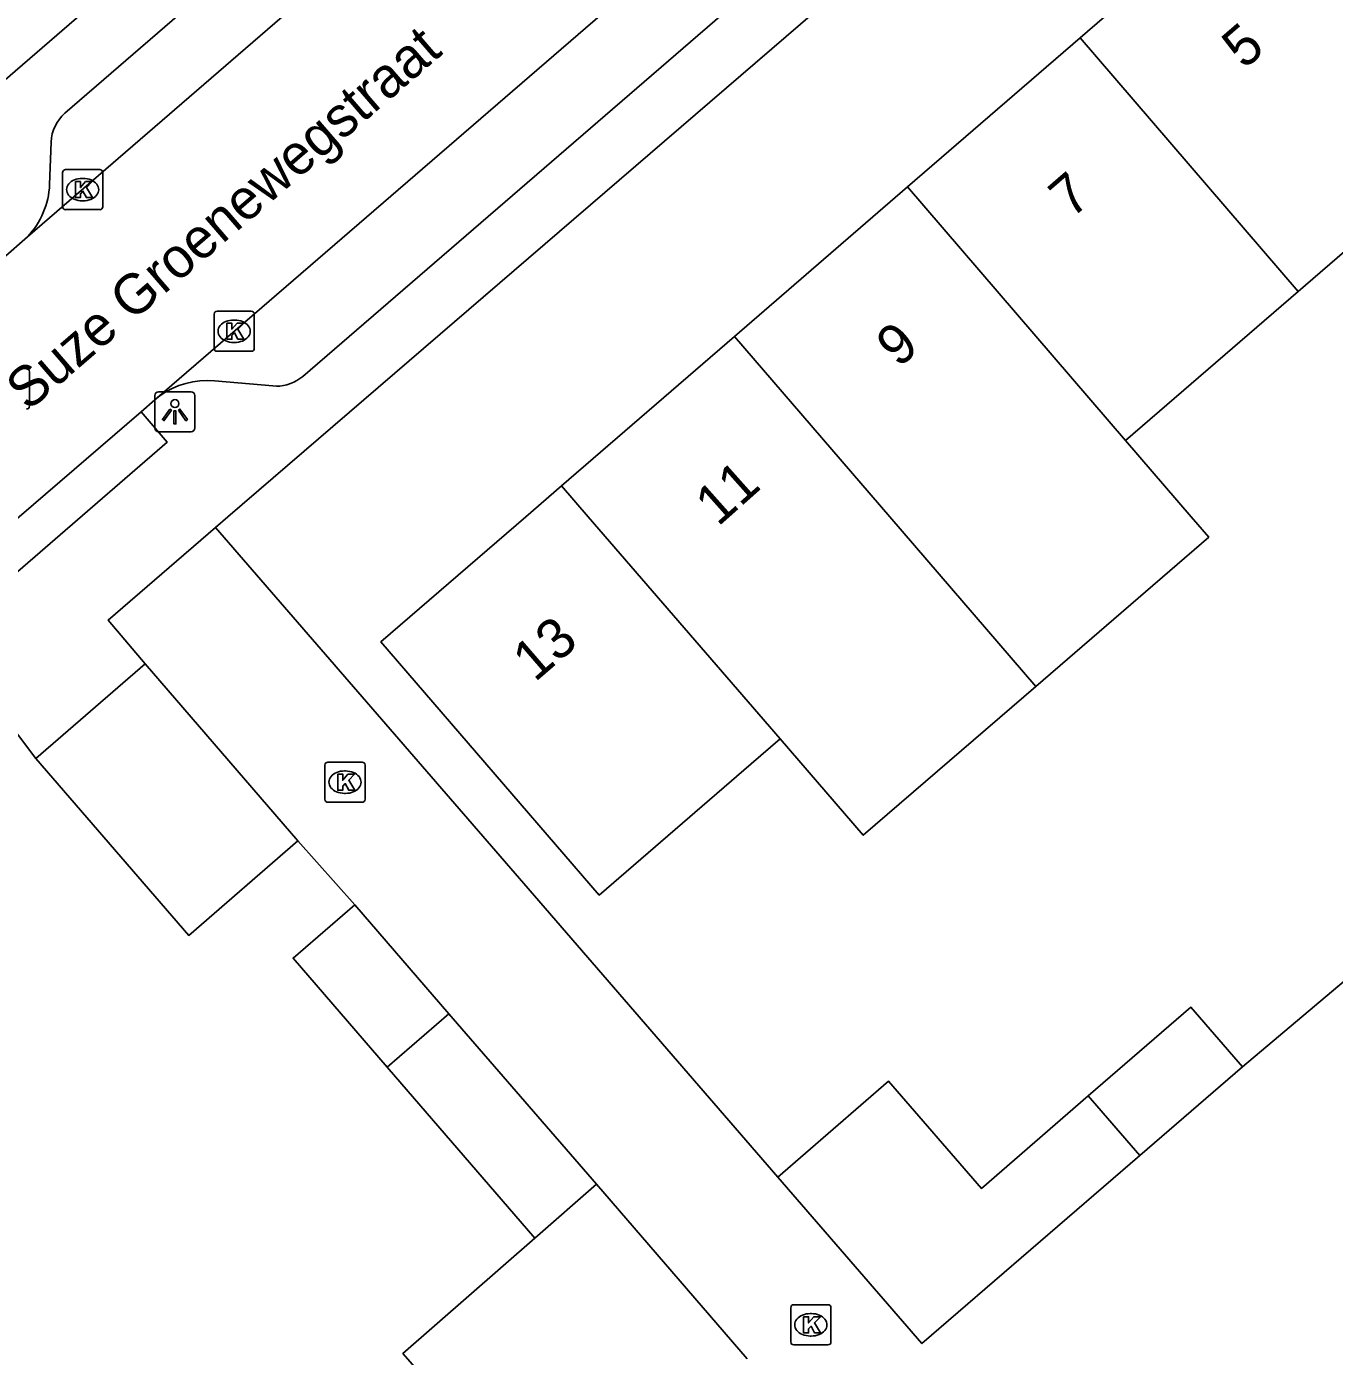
# Model space of a CAD drawing. Extents: x 160304 to 160954, y 383686 to 384161.
# Drawn here: x 160443.23 to 160475.81, y 383979.08 to 384012.21 of the extents above; entities that cross this region are included whole.
import ezdxf

# ---------------------------------------------------------------- set-up
doc = ezdxf.new("R2010")
doc.units = 0
for name, color, linetype in [('IMGEO_Kolk', 7, 'Continuous'), ('IMGEO_Lichtpunt', 7, 'Continuous'), ('IMGEO_Muur', 7, 'Continuous'), ('IMGEO_Openbare_ruimte_label', 7, 'Continuous'), ('IMGEO_Pand', 7, 'Continuous'), ('IMGEO_Pand_nummerreeks', 7, 'Continuous'), ('IMGEO_Rijbaan_lokaal_open', 7, 'Continuous'), ('IMGEO_Rioolput', 7, 'Continuous'), ('IMGEO_Voetpad_open', 7, 'Continuous')]:
    doc.layers.add(name, color=color, linetype=linetype)

msp = doc.modelspace()

# ---------------------------------------------------------------- linework, layer by layer
at = {"layer": 'IMGEO_Kolk'}
for p, q in [((160444.122, 384007.725), (160444.122, 384008.577)), ((160444.197, 384008.651), (160445.049, 384008.651)), ((160445.123, 384008.577), (160445.123, 384007.725)), ((160444.61, 384008.431), (160444.635, 384008.431)), ((160445.049, 384007.651), (160444.197, 384007.651)), ((160444.633, 384007.871), (160444.608, 384007.871)), ((160447.897, 384004.196), (160447.897, 384005.048)), ((160447.972, 384005.122), (160448.824, 384005.122)), ((160448.898, 384005.048), (160448.898, 384004.196)), ((160448.385, 384004.902), (160448.41, 384004.902)), ((160448.408, 384004.342), (160448.383, 384004.342)), ((160448.824, 384004.122), (160447.972, 384004.122)), ((160450.659, 383992.962), (160450.659, 383993.814)), ((160450.734, 383993.888), (160451.586, 383993.888)), ((160451.147, 383993.668), (160451.172, 383993.668)), ((160451.66, 383993.814), (160451.66, 383992.962)), ((160451.17, 383993.108), (160451.145, 383993.108)), ((160451.586, 383992.888), (160450.734, 383992.888)), ((160462.267, 383979.443), (160462.267, 383980.295)), ((160462.342, 383980.369), (160463.194, 383980.369)), ((160462.755, 383980.149), (160462.78, 383980.149)), ((160463.268, 383980.295), (160463.268, 383979.443)), ((160462.778, 383979.589), (160462.753, 383979.589)), ((160463.194, 383979.369), (160462.342, 383979.369))]:
    msp.add_line(p, q, dxfattribs=at)
for points in [[(160444.122, 384007.725), (160444.122, 384008.577)], [(160444.197, 384008.651), (160445.049, 384008.651)], [(160445.123, 384008.577), (160445.123, 384007.725)], [(160444.443, 384008.351), (160444.566, 384008.351), (160444.566, 384008.2), (160444.696, 384008.351), (160444.86, 384008.351), (160444.714, 384008.2), (160444.867, 384007.951), (160444.715, 384007.951), (160444.63, 384008.115), (160444.566, 384008.048), (160444.566, 384007.951), (160444.443, 384007.951), (160444.443, 384008.351)], [(160445.049, 384007.651), (160444.197, 384007.651)], [(160447.897, 384004.196), (160447.897, 384005.048)], [(160447.972, 384005.122), (160448.824, 384005.122)], [(160448.898, 384005.048), (160448.898, 384004.196)], [(160448.218, 384004.822), (160448.341, 384004.822), (160448.341, 384004.671), (160448.471, 384004.822), (160448.635, 384004.822), (160448.489, 384004.671), (160448.642, 384004.422), (160448.49, 384004.422), (160448.405, 384004.586), (160448.341, 384004.519), (160448.341, 384004.422), (160448.218, 384004.422), (160448.218, 384004.822)], [(160448.824, 384004.122), (160447.972, 384004.122)], [(160450.659, 383992.962), (160450.659, 383993.814)], [(160450.734, 383993.888), (160451.586, 383993.888)], [(160451.66, 383993.814), (160451.66, 383992.962)], [(160450.98, 383993.588), (160451.103, 383993.588), (160451.103, 383993.437), (160451.233, 383993.588), (160451.397, 383993.588), (160451.251, 383993.437), (160451.404, 383993.188), (160451.252, 383993.188), (160451.167, 383993.352), (160451.103, 383993.285), (160451.103, 383993.188), (160450.98, 383993.188), (160450.98, 383993.588)], [(160451.586, 383992.888), (160450.734, 383992.888)], [(160462.267, 383979.443), (160462.267, 383980.295)], [(160462.342, 383980.369), (160463.194, 383980.369)], [(160462.588, 383980.069), (160462.711, 383980.069), (160462.711, 383979.918), (160462.841, 383980.069), (160463.005, 383980.069), (160462.859, 383979.918), (160463.012, 383979.669), (160462.86, 383979.669), (160462.775, 383979.833), (160462.711, 383979.766), (160462.711, 383979.669), (160462.588, 383979.669), (160462.588, 383980.069)], [(160463.268, 383980.295), (160463.268, 383979.443)], [(160463.194, 383979.369), (160462.342, 383979.369)]]:
    msp.add_lwpolyline(points, dxfattribs=at)
for centre, start, end in [((160444.199, 384008.575), 91.552, 178.448), ((160444.199, 384008.575), 91.552, 178.448), ((160445.047, 384008.575), 1.552, 88.448), ((160445.047, 384008.575), 1.552, 88.448), ((160444.199, 384007.727), 181.552, 268.448), ((160444.199, 384007.727), 181.552, 268.448), ((160445.047, 384007.727), 271.552, 358.448), ((160445.047, 384007.727), 271.552, 358.448), ((160447.974, 384005.046), 91.552, 178.448), ((160447.974, 384005.046), 91.552, 178.448), ((160448.822, 384005.046), 1.552, 88.448), ((160448.822, 384005.046), 1.552, 88.448), ((160447.974, 384004.198), 181.552, 268.448), ((160447.974, 384004.198), 181.552, 268.448), ((160448.822, 384004.198), 271.552, 358.448), ((160448.822, 384004.198), 271.552, 358.448), ((160450.736, 383993.812), 91.552, 178.448), ((160450.736, 383993.812), 91.552, 178.448), ((160451.584, 383993.812), 1.552, 88.448), ((160451.584, 383993.812), 1.552, 88.448), ((160450.736, 383992.964), 181.552, 268.448), ((160450.736, 383992.964), 181.552, 268.448), ((160451.584, 383992.964), 271.552, 358.448), ((160451.584, 383992.964), 271.552, 358.448), ((160462.344, 383980.293), 91.552, 178.448), ((160462.344, 383980.293), 91.552, 178.448), ((160463.192, 383980.293), 1.552, 88.448), ((160463.192, 383980.293), 1.552, 88.448), ((160462.344, 383979.445), 181.552, 268.448), ((160462.344, 383979.445), 181.552, 268.448), ((160463.192, 383979.445), 271.552, 358.448), ((160463.192, 383979.445), 271.552, 358.448)]:
    msp.add_arc(centre, 0.0765, start, end, dxfattribs=at)
for centre, major_axis, ratio, start_param, end_param in [((160444.609, 384008.151), (-0.387, 0.002), 0.722429, 4.712389, 7.853982), ((160444.634, 384008.151), (-0.39, 0.002), 0.717154, 1.570796, 4.712389), ((160448.384, 384004.622), (-0.387, 0.002), 0.722429, 4.712389, 7.853982), ((160448.409, 384004.622), (-0.39, 0.002), 0.717154, 1.570796, 4.712389), ((160451.146, 383993.388), (-0.387, 0.002), 0.722429, 4.712389, 7.853982), ((160451.171, 383993.388), (-0.39, 0.002), 0.717154, 1.570796, 4.712389), ((160462.754, 383979.869), (-0.387, 0.002), 0.722429, 4.712389, 7.853982), ((160462.779, 383979.869), (-0.39, 0.002), 0.717154, 1.570796, 4.712389)]:
    msp.add_ellipse(centre, major_axis=major_axis, ratio=ratio, start_param=start_param, end_param=end_param, dxfattribs=at)
at = {"layer": 'IMGEO_Lichtpunt'}
for p, q in [((160446.422, 384003.02), (160446.422, 384002.213)), ((160446.422, 384003.02), (160446.422, 384002.213)), ((160447.324, 384003.115), (160446.516, 384003.115)), ((160447.324, 384003.115), (160446.516, 384003.115)), ((160447.418, 384002.213), (160447.418, 384003.02)), ((160447.418, 384002.213), (160447.418, 384003.02)), ((160446.516, 384002.119), (160447.324, 384002.119)), ((160446.516, 384002.119), (160447.324, 384002.119))]:
    msp.add_line(p, q, dxfattribs=at)
for points in [[(160446.796, 384002.684), (160446.835, 384002.656), (160446.647, 384002.394), (160446.609, 384002.421), (160446.796, 384002.684)], [(160446.898, 384002.636), (160446.945, 384002.636), (160446.945, 384002.314), (160446.898, 384002.314), (160446.898, 384002.636)], [(160447.008, 384002.656), (160447.046, 384002.683), (160447.233, 384002.421), (160447.194, 384002.393), (160447.008, 384002.656)]]:
    msp.add_lwpolyline(points, dxfattribs=at)
msp.add_circle((160446.921, 384002.818), 0.0994, dxfattribs=at)
for centre, start, end in [((160446.516, 384003.02), 90, 180), ((160446.516, 384003.02), 90, 180), ((160447.324, 384003.02), 0, 90), ((160447.324, 384003.02), 0, 90), ((160446.516, 384002.213), 180, 270), ((160446.516, 384002.213), 180, 270), ((160447.324, 384002.213), 270, 0), ((160447.324, 384002.213), 270, 360)]:
    msp.add_arc(centre, 0.0946, start, end, dxfattribs=at)
at = {"layer": 'IMGEO_Muur'}
msp.add_lwpolyline([(160461.946, 383983.55), (160455.612, 383990.866)], dxfattribs=at)
at = {"layer": 'IMGEO_Pand'}
for points in [[(160469.478, 384011.932), (160473.784, 384015.651)], [(160465.175, 384008.216), (160469.478, 384011.932)], [(160469.478, 384011.932), (160474.915, 384005.61)], [(160460.864, 384004.492), (160465.175, 384008.216)], [(160465.175, 384008.216), (160470.61, 384001.896)], [(160481.518, 384006.62), (160479.908, 384005.23), (160477.59, 384007.917), (160474.915, 384005.61)], [(160474.915, 384005.61), (160470.61, 384001.896)], [(160456.556, 384000.772), (160460.864, 384004.492)], [(160468.376, 383995.775), (160464.735, 384000), (160460.864, 384004.492)], [(160470.61, 384001.896), (160472.246, 384000), (160472.684, 383999.492), (160468.376, 383995.775)], [(160462, 383994.468), (160461.279, 383993.846), (160457.495, 383990.577), (160452.051, 383996.881), (160455.662, 384000), (160456.556, 384000.772)], [(160462, 383994.468), (160457.223, 384000), (160456.556, 384000.772)], [(160443.455, 383993.98), (160446.178, 383996.332)], [(160446.178, 383996.332), (160449.988, 383991.923)], [(160468.376, 383995.775), (160464.074, 383992.064), (160462, 383994.468)], [(160449.988, 383991.923), (160447.265, 383989.57), (160443.455, 383993.98)], [(160452.212, 383986.286), (160449.864, 383989.004), (160451.404, 383990.334)], [(160451.404, 383990.334), (160453.75, 383987.619)], [(160469.682, 383985.571), (160472.239, 383987.78), (160473.521, 383986.297)], [(160452.212, 383986.286), (160453.75, 383987.619)], [(160453.75, 383987.619), (160457.423, 383983.369)], [(160455.89, 383982.028), (160452.212, 383986.286)], [(160473.521, 383986.297), (160470.963, 383984.088)], [(160461.946, 383983.55), (160464.706, 383985.939), (160467.017, 383983.269), (160469.682, 383985.571)], [(160470.963, 383984.088), (160469.682, 383985.571)], [(160470.963, 383984.088), (160465.537, 383979.401), (160461.946, 383983.55)], [(160455.89, 383982.028), (160457.423, 383983.369)], [(160457.423, 383983.369), (160461.178, 383979.024)], [(160459.641, 383977.685), (160456.376, 383974.841), (160452.604, 383979.153), (160455.89, 383982.028)]]:
    msp.add_lwpolyline(points, dxfattribs=at)
at = {"layer": 'IMGEO_Rijbaan_lokaal_open'}
for points in [[(160471.504, 384031.385), (160443.247, 384006.975)], [(160446.417, 384002.912), (160475.034, 384027.614)], [(160442.642, 384006.44), (160443.247, 384006.975)], [(160440.231, 383997.562), (160443.044, 384000), (160446.077, 384002.618)], [(160446.417, 384002.912), (160446.077, 384002.618)], [(160446.178, 383996.332), (160445.259, 383997.425), (160447.932, 383999.736)], [(160447.932, 383999.736), (160455.612, 383990.866), (160461.946, 383983.55)], [(160451.404, 383990.334), (160449.988, 383991.923)], [(160473.521, 383986.297), (160476.215, 383988.562), (160478.188, 383987.535)]]:
    msp.add_lwpolyline(points, dxfattribs=at)
at = {"layer": 'IMGEO_Rioolput'}
msp.add_line((160443.299, 384003.612), (160443.299, 384002.76), dxfattribs=at)
msp.add_lwpolyline([(160443.299, 384003.612), (160443.299, 384002.76)], dxfattribs=at)
for centre, start, end in [((160443.223, 384003.61), 1.552, 88.448), ((160443.223, 384003.61), 1.552, 88.448), ((160443.223, 384002.762), 271.552, 358.448), ((160443.223, 384002.762), 271.552, 358.448)]:
    msp.add_arc(centre, 0.0765, start, end, dxfattribs=at)
at = {"layer": 'IMGEO_Voetpad_open'}
for points in [[(160460.261, 384032.534), (160463.456, 384028.84), (160440.174, 384008.722)], [(160444.182, 384010.054), (160468.436, 384031.002)], [(160447.932, 383999.736), (160448.239, 384000), (160480.946, 384028.137)], [(160474.103, 384024.212), (160450.105, 384003.496), (160450.035, 384003.441), (160449.96, 384003.392), (160449.882, 384003.35), (160449.799, 384003.316), (160449.714, 384003.288), (160449.627, 384003.269), (160449.539, 384003.257), (160449.45, 384003.254), (160449.361, 384003.258), (160447.905, 384003.39), (160447.725, 384003.398), (160447.545, 384003.389), (160447.366, 384003.365), (160447.19, 384003.324), (160447.019, 384003.268), (160446.853, 384003.197), (160446.694, 384003.111), (160446.543, 384003.012), (160446.417, 384002.912)], [(160443.797, 384008.278), (160443.837, 384009.335)], [(160446.077, 384002.618), (160446.732, 384001.862), (160440.886, 383996.806), (160440.231, 383997.562)], [(160443.455, 383993.98), (160442.593, 383995.12), (160425.555, 383980.472)]]:
    msp.add_lwpolyline(points, dxfattribs=at)
for centre, radius, start, end in [((160444.841, 384009.296), 1.005, 130.9806, 177.7529), ((160441.8, 384008.354), 1.999, 316.3963, 357.8343)]:
    msp.add_arc(centre, radius, start, end, dxfattribs=at)

# ---------------------------------------------------------------- texts
at = {"layer": 'IMGEO_Openbare_ruimte_label'}
msp.add_text('Suze Groenewegstraat', height=1, rotation=40.7816, dxfattribs=at).set_placement((160443.263, 384002.61))
at = {"layer": 'IMGEO_Pand_nummerreeks'}
for s, rotation, p in [('5', 40.8175, (160473.567, 384011.128)), ('7', 40.8175, (160469.26, 384007.409)), ('9', 40.8175, (160464.953, 384003.689)), ('11', 41.6368, (160460.453, 383999.738)), ('13', 40.8175, (160455.891, 383995.863))]:
    msp.add_text(s, height=1, rotation=rotation, dxfattribs=at).set_placement(p)

doc.saveas('drawing.dxf')
